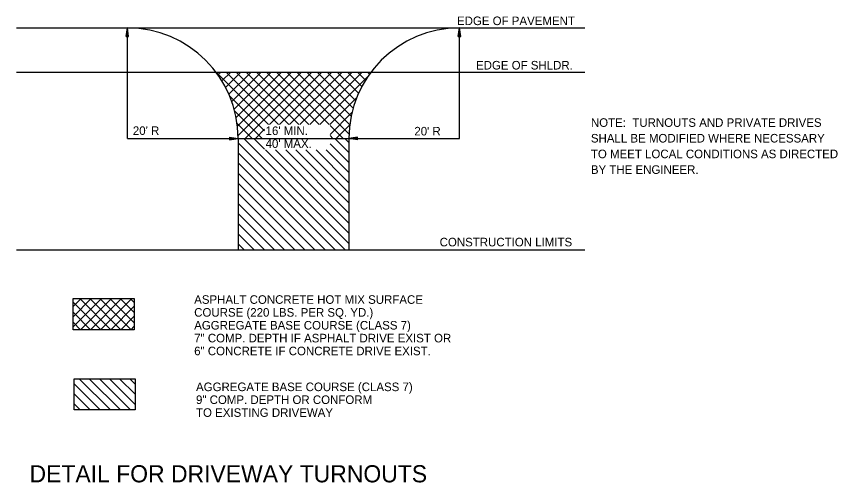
# Model space of a CAD drawing. Extents: x 634177 to 635904, y 289936 to 290970.
# Drawn here: x 635811.3 to 635868.7, y 290770.1 to 290802.7 of the extents above; entities that cross this region are included whole.
import ezdxf

# ---------------------------------------------------------------- set-up
doc = ezdxf.new("R2010")
doc.units = 0
for name, color, linetype in [('Default', 7, 'Continuous'), ('R_Dimension', 7, 'Continuous'), ('R_Draft', 7, 'Continuous')]:
    doc.layers.add(name, color=color, linetype=linetype)

msp = doc.modelspace()

# ---------------------------------------------------------------- linework, layer by layer
at = {"layer": 'R_Dimension'}
for p, q in [((635818.935, 290801.294), (635819.025, 290801.894)), ((635818.935, 290801.294), (635819.025, 290801.894)), ((635818.95, 290801.294), (635819.025, 290801.794)), ((635818.95, 290801.294), (635819.025, 290801.794)), ((635818.965, 290801.294), (635819.025, 290801.691)), ((635818.965, 290801.294), (635819.025, 290801.691)), ((635818.98, 290801.294), (635819.025, 290801.591)), ((635818.98, 290801.294), (635819.025, 290801.591)), ((635819.115, 290801.294), (635819.025, 290801.894)), ((635819.115, 290801.294), (635819.025, 290801.894)), ((635819.1, 290801.294), (635819.025, 290801.794)), ((635819.1, 290801.294), (635819.025, 290801.794)), ((635819.085, 290801.294), (635819.025, 290801.691)), ((635819.085, 290801.294), (635819.025, 290801.691)), ((635819.07, 290801.294), (635819.025, 290801.591)), ((635819.07, 290801.294), (635819.025, 290801.591)), ((635842.18, 290801.294), (635842.27, 290801.894)), ((635842.18, 290801.294), (635842.27, 290801.894)), ((635842.195, 290801.294), (635842.27, 290801.794)), ((635842.195, 290801.294), (635842.27, 290801.794)), ((635842.211, 290801.294), (635842.27, 290801.691)), ((635842.211, 290801.294), (635842.27, 290801.691)), ((635842.226, 290801.294), (635842.27, 290801.591)), ((635842.226, 290801.294), (635842.27, 290801.591)), ((635842.36, 290801.294), (635842.27, 290801.894)), ((635842.36, 290801.294), (635842.27, 290801.894)), ((635842.345, 290801.294), (635842.27, 290801.794)), ((635842.345, 290801.294), (635842.27, 290801.794)), ((635842.33, 290801.294), (635842.27, 290801.691)), ((635842.33, 290801.294), (635842.27, 290801.691)), ((635842.315, 290801.294), (635842.27, 290801.591)), ((635842.315, 290801.294), (635842.27, 290801.591)), ((635818.935, 290801.294), (635819.115, 290801.294)), ((635818.935, 290801.294), (635819.115, 290801.294)), ((635818.996, 290801.294), (635819.025, 290801.489)), ((635818.996, 290801.294), (635819.025, 290801.489)), ((635819.011, 290801.294), (635819.025, 290801.389)), ((635819.011, 290801.294), (635819.025, 290801.389)), ((635819.055, 290801.294), (635819.025, 290801.489)), ((635819.055, 290801.294), (635819.025, 290801.489)), ((635819.039, 290801.294), (635819.025, 290801.389)), ((635819.039, 290801.294), (635819.025, 290801.389)), ((635842.18, 290801.294), (635842.36, 290801.294)), ((635842.18, 290801.294), (635842.36, 290801.294)), ((635842.241, 290801.294), (635842.27, 290801.489)), ((635842.241, 290801.294), (635842.27, 290801.489)), ((635842.256, 290801.294), (635842.27, 290801.389)), ((635842.256, 290801.294), (635842.27, 290801.389)), ((635842.3, 290801.294), (635842.27, 290801.489)), ((635842.3, 290801.294), (635842.27, 290801.489)), ((635842.284, 290801.294), (635842.27, 290801.389)), ((635842.284, 290801.294), (635842.27, 290801.389)), ((635826.174, 290794.236), (635826.774, 290794.146)), ((635826.174, 290794.236), (635826.174, 290794.056)), ((635826.174, 290794.236), (635826.774, 290794.146)), ((635826.174, 290794.236), (635826.174, 290794.056)), ((635826.174, 290794.221), (635826.673, 290794.146)), ((635826.174, 290794.221), (635826.673, 290794.146)), ((635826.174, 290794.206), (635826.57, 290794.146)), ((635826.174, 290794.206), (635826.57, 290794.146)), ((635826.174, 290794.191), (635826.47, 290794.146)), ((635826.174, 290794.191), (635826.47, 290794.146)), ((635826.174, 290794.175), (635826.369, 290794.146)), ((635826.174, 290794.175), (635826.369, 290794.146)), ((635826.174, 290794.16), (635826.268, 290794.146)), ((635826.174, 290794.16), (635826.268, 290794.146)), ((635826.174, 290794.056), (635826.774, 290794.146)), ((635826.174, 290794.116), (635826.369, 290794.146)), ((635826.174, 290794.086), (635826.57, 290794.146)), ((635826.174, 290794.071), (635826.673, 290794.146)), ((635826.174, 290794.101), (635826.47, 290794.146)), ((635826.174, 290794.132), (635826.268, 290794.146)), ((635826.174, 290794.056), (635826.774, 290794.146)), ((635826.174, 290794.116), (635826.369, 290794.146)), ((635826.174, 290794.086), (635826.57, 290794.146)), ((635826.174, 290794.071), (635826.673, 290794.146)), ((635826.174, 290794.101), (635826.47, 290794.146)), ((635826.174, 290794.132), (635826.268, 290794.146)), ((635835.122, 290794.236), (635834.522, 290794.146)), ((635835.122, 290794.236), (635834.522, 290794.146)), ((635835.122, 290794.056), (635834.522, 290794.146)), ((635835.122, 290794.056), (635834.522, 290794.146)), ((635835.122, 290794.221), (635834.622, 290794.146)), ((635835.122, 290794.221), (635834.622, 290794.146)), ((635835.122, 290794.071), (635834.622, 290794.146)), ((635835.122, 290794.071), (635834.622, 290794.146)), ((635835.122, 290794.206), (635834.725, 290794.146)), ((635835.122, 290794.206), (635834.725, 290794.146)), ((635835.122, 290794.086), (635834.725, 290794.146)), ((635835.122, 290794.086), (635834.725, 290794.146)), ((635835.122, 290794.191), (635834.825, 290794.146)), ((635835.122, 290794.191), (635834.825, 290794.146)), ((635835.122, 290794.101), (635834.825, 290794.146)), ((635835.122, 290794.101), (635834.825, 290794.146)), ((635835.122, 290794.175), (635834.927, 290794.146)), ((635835.122, 290794.175), (635834.927, 290794.146)), ((635835.122, 290794.117), (635834.927, 290794.146)), ((635835.122, 290794.117), (635834.927, 290794.146)), ((635835.122, 290794.16), (635835.027, 290794.146)), ((635835.122, 290794.16), (635835.027, 290794.146)), ((635835.122, 290794.132), (635835.027, 290794.146)), ((635835.122, 290794.132), (635835.027, 290794.146)), ((635835.122, 290794.056), (635835.122, 290794.236)), ((635835.122, 290794.056), (635835.122, 290794.236))]:
    msp.add_line(p, q, dxfattribs=at)
at = {"layer": 'R_Draft'}
for p, q in [((635811.264, 290801.894), (635851.038, 290801.894)), ((635819.025, 290794.146), (635819.025, 290801.894)), ((635842.27, 290794.146), (635842.27, 290801.894)), ((635811.264, 290798.795), (635851.038, 290798.795)), ((635828.898, 290795.124), (635825.228, 290798.795)), ((635825.361, 290798.597), (635825.559, 290798.795)), ((635825.641, 290798.17), (635826.266, 290798.795)), ((635825.896, 290797.718), (635826.973, 290798.795)), ((635829.606, 290795.124), (635825.935, 290798.795)), ((635826.125, 290797.24), (635827.681, 290798.795)), ((635826.325, 290796.733), (635828.388, 290798.795)), ((635826.494, 290796.194), (635829.095, 290798.795)), ((635826.628, 290795.621), (635829.802, 290798.795)), ((635830.313, 290795.124), (635826.642, 290798.795)), ((635826.721, 290795.007), (635830.509, 290798.795)), ((635826.767, 290794.346), (635831.216, 290798.795)), ((635827.274, 290794.146), (635831.923, 290798.795)), ((635831.02, 290795.124), (635827.349, 290798.795)), ((635831.727, 290795.124), (635828.056, 290798.795)), ((635832.434, 290795.124), (635828.763, 290798.795)), ((635828.96, 290795.124), (635832.63, 290798.795)), ((635833.141, 290795.124), (635829.471, 290798.795)), ((635829.667, 290795.124), (635833.337, 290798.795)), ((635834.533, 290794.44), (635830.178, 290798.795)), ((635830.374, 290795.124), (635834.045, 290798.795)), ((635834.585, 290795.095), (635830.885, 290798.795)), ((635831.081, 290795.124), (635834.752, 290798.795)), ((635834.683, 290795.704), (635831.592, 290798.795)), ((635831.788, 290795.124), (635835.459, 290798.795)), ((635834.822, 290796.272), (635832.299, 290798.795)), ((635834.995, 290796.806), (635833.006, 290798.795)), ((635835.2, 290797.309), (635833.713, 290798.795)), ((635835.432, 290797.783), (635834.42, 290798.795)), ((635835.691, 290798.231), (635835.127, 290798.795)), ((635835.974, 290798.655), (635835.834, 290798.795)), ((635832.495, 290795.124), (635835.854, 290798.483)), ((635828.625, 290794.691), (635826.16, 290797.156)), ((635833.202, 290795.124), (635835.066, 290796.988)), ((635828.463, 290794.146), (635826.521, 290796.087)), ((635833.21, 290794.425), (635834.74, 290795.955)), ((635827.756, 290794.146), (635826.7, 290795.201)), ((635827.981, 290794.146), (635828.625, 290794.79)), ((635834.12, 290794.146), (635833.21, 290795.055)), ((635833.638, 290794.146), (635834.584, 290795.092)), ((635819.025, 290794.146), (635826.774, 290794.146)), ((635826.774, 290794.146), (635826.774, 290786.346)), ((635826.774, 290794.146), (635834.522, 290794.146)), ((635834.522, 290786.802), (635827.178, 290794.146)), ((635828.625, 290793.406), (635827.885, 290794.146)), ((635828.625, 290794.113), (635828.592, 290794.146)), ((635833.412, 290794.146), (635833.21, 290794.348)), ((635834.522, 290793.166), (635833.542, 290794.146)), ((635834.522, 290793.873), (635834.249, 290794.146)), ((635834.522, 290794.146), (635834.522, 290786.346)), ((635834.522, 290794.146), (635842.27, 290794.146)), ((635834.271, 290786.346), (635826.774, 290793.843)), ((635834.522, 290792.459), (635833.21, 290793.77)), ((635833.564, 290786.346), (635826.774, 290793.136)), ((635834.522, 290787.509), (635828.693, 290793.338)), ((635834.522, 290788.216), (635829.4, 290793.338)), ((635834.522, 290788.923), (635830.107, 290793.338)), ((635834.522, 290789.63), (635830.815, 290793.338)), ((635834.522, 290790.337), (635831.522, 290793.338)), ((635834.522, 290791.045), (635832.229, 290793.338)), ((635834.522, 290791.752), (635832.936, 290793.338)), ((635832.857, 290786.346), (635826.774, 290792.429)), ((635832.149, 290786.346), (635826.774, 290791.722)), ((635831.442, 290786.346), (635826.774, 290791.015)), ((635830.735, 290786.346), (635826.774, 290790.308)), ((635830.028, 290786.346), (635826.774, 290789.601)), ((635829.321, 290786.346), (635826.774, 290788.893)), ((635828.614, 290786.346), (635826.774, 290788.186)), ((635827.907, 290786.346), (635826.774, 290787.479)), ((635827.2, 290786.346), (635826.774, 290786.772)), ((635811.264, 290786.346), (635851.038, 290786.346)), ((635815.229, 290782.371), (635815.798, 290782.941)), ((635815.229, 290781.664), (635816.505, 290782.941)), ((635815.229, 290780.957), (635817.212, 290782.941)), ((635817.165, 290780.759), (635815.229, 290782.695)), ((635817.872, 290780.759), (635815.69, 290782.941)), ((635815.737, 290780.759), (635817.919, 290782.941)), ((635818.579, 290780.759), (635816.397, 290782.941)), ((635816.444, 290780.759), (635818.626, 290782.941)), ((635819.286, 290780.759), (635817.104, 290782.941)), ((635817.151, 290780.759), (635819.333, 290782.941)), ((635819.509, 290781.242), (635817.811, 290782.941)), ((635819.509, 290781.95), (635818.518, 290782.941)), ((635819.509, 290782.657), (635819.225, 290782.941)), ((635816.458, 290780.759), (635815.229, 290781.988)), ((635817.859, 290780.759), (635819.509, 290782.41)), ((635818.566, 290780.759), (635819.509, 290781.703)), ((635815.751, 290780.759), (635815.229, 290781.281)), ((635819.273, 290780.759), (635819.509, 290780.995)), ((635817.132, 290775.143), (635815.297, 290776.978)), ((635817.839, 290775.143), (635815.657, 290777.325)), ((635818.546, 290775.143), (635816.364, 290777.325)), ((635819.253, 290775.143), (635817.071, 290777.325)), ((635819.578, 290775.526), (635817.778, 290777.325)), ((635819.578, 290776.233), (635818.485, 290777.325)), ((635819.578, 290776.94), (635819.193, 290777.325)), ((635816.425, 290775.143), (635815.297, 290776.271)), ((635815.718, 290775.143), (635815.297, 290775.564))]:
    msp.add_line(p, q, dxfattribs=at)
for points in [[(635815.229, 290782.941), (635819.509, 290782.941), (635819.509, 290780.759), (635815.229, 290780.759)], [(635815.297, 290777.325), (635819.578, 290777.325), (635819.578, 290775.143), (635815.297, 290775.143)]]:
    msp.add_lwpolyline(points, close=True, dxfattribs=at)
for centre, start, end in [((635819.025, 290794.146), 0, 90), ((635842.27, 290794.146), 90, 180)]:
    msp.add_arc(centre, 7.748, start, end, dxfattribs=at)

# ---------------------------------------------------------------- texts
at = {"layer": 'Default'}
for s, p in [('NOTE:  TURNOUTS AND PRIVATE DRIVES', (635851.457, 290794.959)), ('SHALL BE MODIFIED WHERE NECESSARY', (635851.457, 290793.862)), ('TO MEET LOCAL CONDITIONS AS DIRECTED', (635851.457, 290792.764)), ('BY THE ENGINEER.', (635851.457, 290791.667))]:
    msp.add_text(s, height=0.6, dxfattribs=at).set_placement(p)
at = {"layer": 'R_Draft'}
for s, height, p in [('EDGE OF PAVEMENT', 0.6, (635842.088, 290802.081)), ('EDGE OF SHLDR.', 0.6, (635843.419, 290798.973)), ("20' R", 0.6, (635819.412, 290794.393)), ("16' MIN.", 0.6, (635828.697, 290794.387)), ("20' R", 0.6, (635839.104, 290794.355)), ("40' MAX.", 0.6, (635828.697, 290793.487)), ('CONSTRUCTION LIMITS', 0.6, (635840.875, 290786.59)), ('ASPHALT CONCRETE HOT MIX SURFACE', 0.6, (635823.701, 290782.568)), ('COURSE (220 LBS. PER SQ. YD.) ', 0.6, (635823.701, 290781.668)), ('AGGREGATE BASE COURSE (CLASS 7) ', 0.6, (635823.701, 290780.768)), ('7" COMP. DEPTH IF ASPHALT DRIVE EXIST OR', 0.6, (635823.701, 290779.868)), ('6" CONCRETE IF CONCRETE DRIVE EXIST.', 0.6, (635823.701, 290778.968)), ('AGGREGATE BASE COURSE (CLASS 7)', 0.6, (635823.83, 290776.456)), ('9" COMP. DEPTH OR CONFORM', 0.6, (635823.83, 290775.556)), ('TO EXISTING DRIVEWAY', 0.6, (635823.83, 290774.656)), ('DETAIL FOR DRIVEWAY TURNOUTS', 1.2, (635812.181, 290770.07))]:
    msp.add_text(s, height=height, dxfattribs=at).set_placement(p)

doc.saveas('drawing.dxf')
